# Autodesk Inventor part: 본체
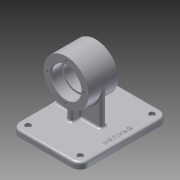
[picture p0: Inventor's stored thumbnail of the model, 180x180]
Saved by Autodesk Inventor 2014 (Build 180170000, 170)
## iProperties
Created: 2019-09
Part Number: 본체
Material: 알루미늄 6061
Document SubType Name: Modeling
Designer: kh
Density: 2.71 g/cm^3
Appearance: 알루미늄 - 평지
Mass: 556.603 g
Surface Area: 496.148 cm^2
Volume: 205.388 cm^3
Author: kh
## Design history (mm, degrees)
sketch "스케치1"
  geometry: C1 r 32 at (0, 0); 1 further point
  constraints: 1 centre point, 1 coincident
  dimensions: "d0" = 64 diameter of C1
extrude "돌출1" new body sketch "스케치1" distance "d1" = 42; taper "d2" = 0 deg
node "작업 평면1"
sketch "스케치2"
  geometry: L1 (-62, 84)-(36, 84); L2 (36, 84)-(36, -42); L3 (36, -42)-(-62, -42); L4 (-62, -42)-(-62, 84); L5 (32, 42)-(-32, 42) reference; L6 (-32, 0)-(-32, 42) reference; 3 further points
  constraints: 8 end point, 2 midpoint, 2 parallel, 1 horizontal, 1 perpendicular
  dimensions: "d4" = 98 distance of L1.start L1.end; "d5" = 126 distance of L1.end L2.end; "d6" = 62 distance from line of point (0, 42) L4; "d7" = 63 distance from line of L1 point (-32, 21)
extrude "돌출2" join sketch "스케치2" distance "d8" = 9; taper "d9" = 0 deg
sketch "스케치3"
  geometry: C1 r 21 at (0, 0); 1 further point
  constraints: 1 centre point, 1 coincident
  dimensions: "d10" = 42 diameter of C1
extrude "돌출3" cut sketch "스케치3" distance "d11" = 15; taper "d12" = 0 deg
sketch "스케치4"
  geometry: 1 further point
hole "구멍1" sketch "스케치4" at (0, 0) diameter "d13" = 36; stored, may be unused: countersink angle "d17" = 82 deg, drill point angle "d19" = 0 deg; dims "d14" = 19.05, "d15" = 42, "d16" = 15, "d18" = 12
node "작업 평면2"
sketch "스케치5"
  geometry: L1 (-32, 0)-(-32, 42) reference; L2 (-50, -42)-(-50, 84) reference; L3 (-26.204, 38)-(-50, 38); L4 (-26.204, 4)-(-50, 4); L5 (-26.204, 38)-(-26.204, 4); 2 further points
  constraints: 6 end point, 3 perpendicular, 2 point on line, 1 midpoint
  dimensions: "d21" = 17 distance from line of point (-32, 21) L3; "d22" = 17 distance from line of point (-32, 21) L4; "d23" = 23.79616 distance between parallel lines of L2 L5
extrude "돌출4" join sketch "스케치5" distance "d24" = 4; taper "d26" = 0 deg; dims "d25" = 4, "d27" = 0
node "작업 평면3"
sketch "스케치6"
  geometry: L1 (62, -50)-(-36, -50) reference; L2 (-32, 0)-(-32, -50); L3 (32, 0)-(32, -50); L4 (-29.773, -50)-(32, -50); A1 r 32 centre (0, 0) between (-32, 0) and (32, 0) reference; A2 r 32 centre (0, 0) between (-32, 0) and (32, 0); 1 further point
  constraints: 6 end point, 4 point on circle, 4 tangent, 3 point on line, 2 perpendicular, 1 centre point, 1 collinear
extrude "돌출5" join sketch "스케치6" distance "d29" = 4; taper "d31" = 0 deg; dims "d30" = 4, "d32" = 0
sketch "스케치7"
  geometry: A1 r 26 centre (0, 0) between (0, 26) and (26, 0); 3 further points
  constraints: 4 point on circle, 2 horizontal alignment, 2 vertical alignment, 1 centre point, 1 coincident
  dimensions: "d33" = 52 diameter of A1
hole "구멍2" sketch "스케치7" at (0, 26), (26, 0), (0, -26), (-26, 0) diameter "d34" = 3.2512; stored, may be unused: countersink angle "d38" = 82 deg, drill point angle "d40" = 118 deg; dims "d35" = 8, "d36" = 9.525, "d37" = 6.35, "d39" = 10
sketch "스케치8"
  geometry: C1 r 1.626 at (0, 26) reference; C2 r 1.626 at (26, 0) reference; C3 r 1.626 at (0, -26) reference; C4 r 1.626 at (-26, 0) reference; 1 further point
hole "구멍3" sketch "스케치8" at (0, 26), (-26, 0), (0, -26), (26, 0) diameter "d41" = 3.2512; stored, may be unused: countersink angle "d45" = 82 deg, drill point angle "d47" = 118 deg; dims "d42" = 8, "d43" = 9.525, "d44" = 6.35, "d46" = 10
fillet "모깎기1" dims "d48" = 3
fillet "모깎기2" dims "d49" = 3
fillet "모깎기3" dims "d50" = 12
sketch "스케치9"
  geometry: L1 (62, -72)-(62, 30) reference; L2 (-36, 30)-(-36, -72) reference; L3 (-24, -84)-(50, -84) reference; L4 (50, 42)-(-24, 42) reference; 5 further points
  constraints: 2 horizontal alignment
  dimensions: "d51" = 12 distance from line of L1 point (50, 30); "d52" = 12 distance from line of point (-24, 30) L2; "d53" = 12 distance from line of L1 point (50, -72); "d54" = 12 distance from line of point (-24, -72) L2; "d56" = 12 distance from line of point (-24, -72) L3; "d57" = 12 distance from line of point (-24, 30) L4
hole "구멍4" sketch "스케치9" at (50, 30), (-24, 30), (50, -72), (-24, -72) diameter "d58" = 4.5; stored, may be unused: countersink angle "d62" = 82 deg, drill point angle "d64" = 0 deg; dims "d59" = 8, "d60" = 8, "d61" = 4.4, "d63" = 10
chamfer "모따기1" distance "d65" = 1; stored, may be unused: second distance "d66" = 3.175, angle "d67" = 45 deg
fillet "모깎기4" dims "d68" = 3
fillet "모깎기5" dims "d69" = 0.3
sketch "스케치10"
  geometry: L1 (55.004, -0.245)-(55.004, -41.755); L2 (55.004, -41.755)-(48.996, -41.755); L3 (48.996, -41.755)-(48.996, -0.245); L4 (48.996, -0.245)-(55.004, -0.245); L5 (-36, -26.472)-(-36, -72) reference; L6 (-24, -84)-(50, -84) reference; L7 (62, -72)-(62, 30) reference; 3 further points
  constraints: 2 midpoint, 1 parallel, 2 other
  dimensions: "d70" = 63 distance from line of point (55.004, -21) L6; "d71" = 10 distance from line of L7 point (52, -41.755); "d72" = 6.00863 distance between parallel lines of L1 L3; "d73" = 41.51049 distance from line of L4 point (52, -41.755)
extrude "돌출6" join sketch "스케치10" distance "d74" = 0.5; taper "d75" = 0 deg
node "솔리드1"
other parameters: "d3" = -59, "d20" = 0, "d28" = 21
